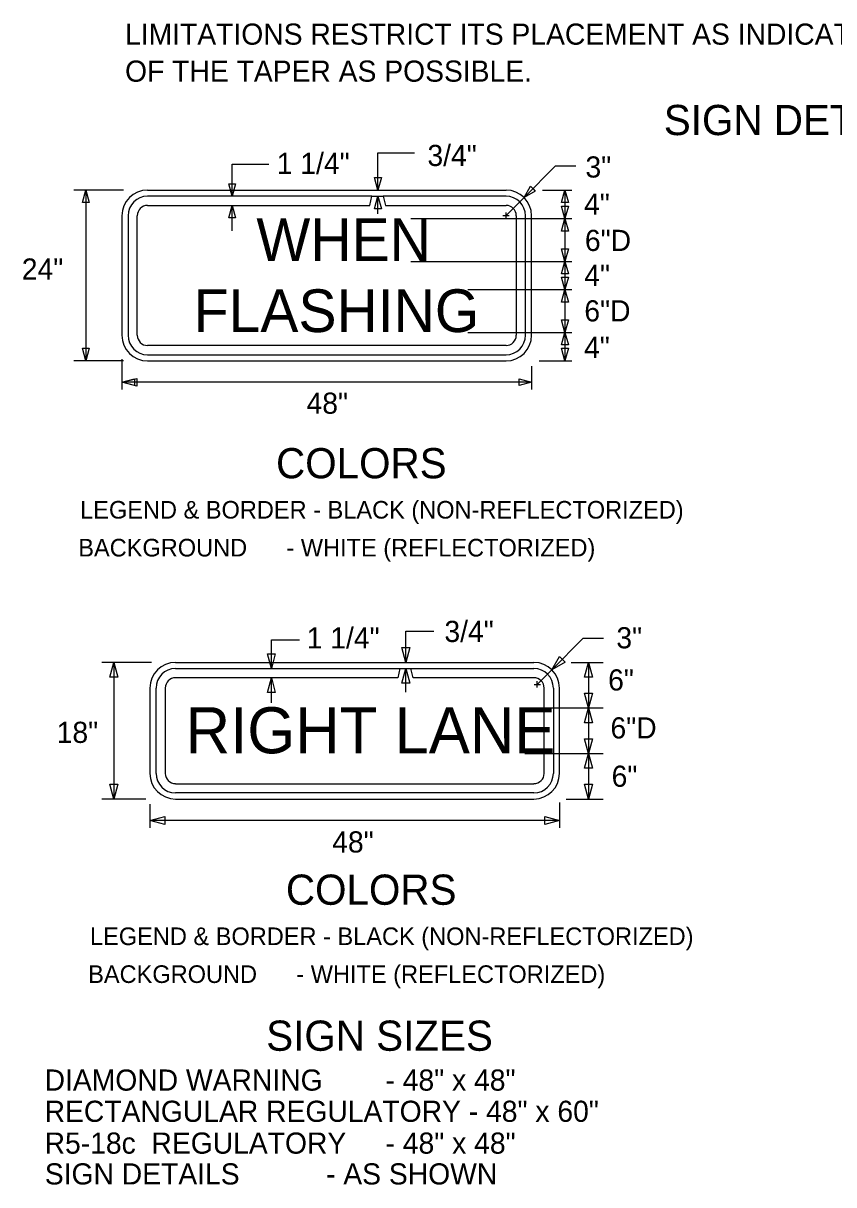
# Model space of a CAD drawing. Extents: x 15273 to 18137, y 1908 to 6555.
# Drawn here: x 17423.1 to 17745.2, y 2205.8 to 2667.1 of the extents above; entities that cross this region are included whole.
import ezdxf

# ---------------------------------------------------------------- set-up
doc = ezdxf.new("R2010")
doc.units = 0
for name, color, linetype in [('MT_SCRATCH_LEVEL_A', 7, 'Continuous'), ('TYPICAL_EX', 7, 'Continuous'), ('TYPICAL_TEXT_DIMEN_EX', 7, 'Continuous'), ('TYPICAL_TEXT_DIMEN_PR', 7, 'Continuous')]:
    doc.layers.add(name, color=color, linetype=linetype)

msp = doc.modelspace()

# ---------------------------------------------------------------- linework, layer by layer
at = {"layer": 'MT_SCRATCH_LEVEL_A'}
for p, q in [((17564.09, 2615.63), (17578.64, 2615.63)), ((17506.14, 2611.09), (17520.69, 2611.09)), ((17622.1, 2597.88), (17634.45, 2610.29)), ((17642.65, 2610.29), (17634.45, 2610.29)), ((17614.95, 2590.7), (17622.1, 2597.88)), ((17613.7, 2590.7), (17616.2, 2590.7)), ((17614.95, 2589.48), (17614.95, 2591.98)), ((17462.36, 2533.67), (17462.36, 2521.59)), ((17625.12, 2530.95), (17625.12, 2521.59)), ((17625.12, 2524.5), (17462.36, 2524.5)), ((17521.73, 2422.2), (17532.87, 2422.2)), ((17575.18, 2425.68), (17586.32, 2425.68)), ((17633.19, 2410.29), (17645.53, 2422.68)), ((17653.7, 2422.68), (17645.53, 2422.68)), ((17627.39, 2404.47), (17633.19, 2410.29)), ((17626.1, 2404.47), (17628.64, 2404.47)), ((17627.39, 2403.25), (17627.39, 2405.73)), ((17636.2, 2357.54), (17636.2, 2347.55)), ((17473.48, 2356.96), (17473.48, 2347.55)), ((17636.2, 2350.47), (17473.48, 2350.47))]:
    msp.add_line(p, q, dxfattribs=at)
at = {"layer": 'TYPICAL_EX'}
for p, q in [((17472.54, 2600.84), (17614.95, 2600.84)), ((17561.68, 2598.4), (17472.54, 2598.4)), ((17560.86, 2594.74), (17561.68, 2598.4)), ((17561.68, 2598.4), (17566.09, 2598.4)), ((17614.95, 2598.4), (17566.09, 2598.4)), ((17566.09, 2598.4), (17567.03, 2594.74)), ((17472.54, 2594.74), (17560.86, 2594.74)), ((17567.03, 2594.74), (17614.95, 2594.74)), ((17462.36, 2590.67), (17462.36, 2543.19)), ((17464.81, 2590.67), (17464.81, 2543.19)), ((17468.47, 2543.19), (17468.47, 2590.67)), ((17619.02, 2590.67), (17619.02, 2543.19)), ((17622.68, 2543.19), (17622.68, 2590.67)), ((17625.12, 2543.19), (17625.12, 2590.67)), ((17614.95, 2539.12), (17472.54, 2539.12)), ((17472.54, 2535.46), (17614.95, 2535.46)), ((17472.54, 2533.02), (17614.95, 2533.02)), ((17483.65, 2413.25), (17626.03, 2413.25)), ((17483.65, 2410.81), (17572.78, 2410.81)), ((17572.78, 2410.81), (17571.96, 2407.15)), ((17572.78, 2410.81), (17577.18, 2410.81)), ((17571.96, 2407.15), (17483.65, 2407.15)), ((17473.48, 2403.08), (17473.48, 2369.15)), ((17475.92, 2369.15), (17475.92, 2403.08)), ((17479.58, 2403.08), (17479.58, 2369.15)), ((17636.2, 2369.15), (17636.2, 2403.08)), ((17483.65, 2365.08), (17626.03, 2365.08)), ((17626.03, 2361.42), (17483.65, 2361.42)), ((17483.65, 2358.98), (17626.03, 2358.98))]:
    msp.add_line(p, q, dxfattribs=at)
for centre, radius, start, end in [((17472.54, 2590.67), 10.17, 90, 180), ((17472.54, 2590.67), 7.73, 90, 180), ((17614.95, 2590.67), 10.17, 0, 90), ((17614.95, 2590.67), 7.73, 0, 90), ((17472.54, 2590.67), 4.07, 90, 180), ((17614.95, 2590.67), 4.07, 0, 90), ((17472.54, 2543.18), 10.17, 180, 270), ((17472.54, 2543.18), 7.73, 180, 270), ((17472.54, 2543.18), 4.07, 180, 270), ((17614.95, 2543.18), 10.17, 270, 0), ((17614.95, 2543.18), 4.07, 270, 0), ((17614.95, 2543.18), 7.73, 270, 0), ((17483.65, 2403.08), 10.17, 90, 180), ((17626.03, 2403.08), 10.17, 0, 90), ((17483.65, 2403.08), 7.73, 90, 180), ((17483.65, 2403.08), 4.07, 90, 180), ((17483.65, 2369.16), 10.17, 180, 270), ((17483.65, 2369.16), 7.73, 180, 270), ((17483.65, 2369.16), 4.07, 180, 270), ((17626.03, 2369.16), 10.17, 270, 0), ((17626.03, 2369.16), 7.73, 270, 0), ((17626.03, 2369.16), 4.07, 270, 0)]:
    msp.add_arc(centre, radius, start, end, dxfattribs=at)
at = {"layer": 'TYPICAL_TEXT_DIMEN_PR'}
for p, q in [((17564.09, 2600.84), (17564.09, 2615.63)), ((17506.14, 2598.4), (17506.14, 2611.09)), ((17506.14, 2598.4), (17504.81, 2603.38)), ((17504.81, 2603.38), (17506.14, 2603.38)), ((17506.14, 2603.38), (17507.48, 2603.38)), ((17507.48, 2603.38), (17506.14, 2598.4)), ((17564.09, 2600.84), (17562.75, 2605.83)), ((17562.75, 2605.83), (17564.09, 2605.83)), ((17564.09, 2605.83), (17565.42, 2605.83)), ((17565.42, 2605.83), (17564.09, 2600.84)), ((17622.1, 2597.89), (17624.67, 2602.36)), ((17624.67, 2602.36), (17625.62, 2601.42)), ((17463.02, 2600.84), (17443.27, 2600.84)), ((17446.66, 2595.86), (17448, 2600.84)), ((17448, 2600.84), (17448, 2533.02)), ((17448, 2600.84), (17449.33, 2595.86)), ((17562.75, 2593.42), (17564.09, 2598.4)), ((17564.09, 2591.37), (17564.09, 2598.4)), ((17564.09, 2598.4), (17565.42, 2593.42)), ((17626.56, 2600.48), (17622.1, 2597.89)), ((17625.62, 2601.42), (17626.56, 2600.48)), ((17629.39, 2600.84), (17641.08, 2600.84)), ((17637.05, 2595.86), (17638.38, 2600.84)), ((17638.38, 2600.84), (17638.38, 2589.52)), ((17638.38, 2600.84), (17639.72, 2595.86)), ((17448, 2595.86), (17446.66, 2595.86)), ((17449.33, 2595.86), (17448, 2595.86)), ((17504.81, 2589.76), (17506.14, 2594.74)), ((17506.14, 2584.65), (17506.14, 2594.74)), ((17506.14, 2594.74), (17507.48, 2589.76)), ((17564.09, 2593.42), (17562.75, 2593.42)), ((17565.42, 2593.42), (17564.09, 2593.42)), ((17638.38, 2595.86), (17637.05, 2595.86)), ((17638.38, 2589.52), (17637.05, 2594.51)), ((17637.05, 2594.51), (17638.38, 2594.51)), ((17639.72, 2595.86), (17638.38, 2595.86)), ((17638.38, 2594.51), (17639.72, 2594.51)), ((17639.72, 2594.51), (17638.38, 2589.52)), ((17506.14, 2589.76), (17504.81, 2589.76)), ((17507.48, 2589.76), (17506.14, 2589.76)), ((17577.18, 2589.52), (17641.08, 2589.52)), ((17637.05, 2584.54), (17638.38, 2589.52)), ((17638.38, 2589.52), (17638.38, 2572.54)), ((17638.38, 2589.52), (17639.72, 2584.54)), ((17638.38, 2584.54), (17637.05, 2584.54)), ((17639.72, 2584.54), (17638.38, 2584.54)), ((17638.38, 2572.54), (17637.05, 2577.53)), ((17637.05, 2577.53), (17638.38, 2577.53)), ((17638.38, 2577.53), (17639.72, 2577.53)), ((17639.72, 2577.53), (17638.38, 2572.54)), ((17577.18, 2572.54), (17641.08, 2572.54)), ((17637.05, 2567.56), (17638.38, 2572.54)), ((17638.38, 2572.54), (17638.38, 2561.32)), ((17638.38, 2572.54), (17639.72, 2567.56)), ((17638.38, 2567.56), (17637.05, 2567.56)), ((17638.38, 2561.32), (17637.05, 2566.3)), ((17637.05, 2566.3), (17638.38, 2566.3)), ((17638.38, 2561.32), (17637.05, 2566.3)), ((17637.05, 2566.3), (17638.38, 2566.3)), ((17639.72, 2567.56), (17638.38, 2567.56)), ((17638.38, 2566.3), (17639.72, 2566.3)), ((17639.72, 2566.3), (17638.38, 2561.32)), ((17638.38, 2566.3), (17639.72, 2566.3)), ((17639.72, 2566.3), (17638.38, 2561.32)), ((17599.79, 2561.32), (17641.08, 2561.32)), ((17637.05, 2556.33), (17638.38, 2561.32)), ((17638.38, 2561.32), (17638.38, 2544.34)), ((17638.38, 2561.32), (17639.72, 2556.33)), ((17638.38, 2556.33), (17637.05, 2556.33)), ((17639.72, 2556.33), (17638.38, 2556.33)), ((17638.38, 2544.34), (17637.05, 2549.32)), ((17637.05, 2549.32), (17638.38, 2549.32)), ((17638.38, 2544.34), (17637.05, 2549.32)), ((17637.05, 2549.32), (17638.38, 2549.32)), ((17638.38, 2549.32), (17639.72, 2549.32)), ((17639.72, 2549.32), (17638.38, 2544.34)), ((17638.38, 2549.32), (17639.72, 2549.32)), ((17639.72, 2549.32), (17638.38, 2544.34)), ((17599.79, 2544.34), (17641.08, 2544.34)), ((17637.05, 2539.35), (17638.38, 2544.34)), ((17638.38, 2544.34), (17638.38, 2533.02)), ((17638.38, 2544.34), (17639.72, 2539.35)), ((17448, 2533.02), (17446.66, 2538)), ((17446.66, 2538), (17448, 2538)), ((17448, 2538), (17449.33, 2538)), ((17449.33, 2538), (17448, 2533.02)), ((17638.38, 2539.35), (17637.05, 2539.35)), ((17638.38, 2533.02), (17637.05, 2538)), ((17637.05, 2538), (17638.38, 2538)), ((17639.72, 2539.35), (17638.38, 2539.35)), ((17638.38, 2538), (17639.72, 2538)), ((17639.72, 2538), (17638.38, 2533.02)), ((17463.02, 2533.02), (17443.27, 2533.02)), ((17628.14, 2533.02), (17641.08, 2533.02)), ((17462.36, 2524.5), (17468.22, 2526.07)), ((17462.36, 2524.5), (17467.35, 2525.84)), ((17468.22, 2522.93), (17462.36, 2524.5)), ((17467.35, 2523.17), (17462.36, 2524.5)), ((17467.35, 2525.84), (17467.35, 2524.5)), ((17467.35, 2524.5), (17467.35, 2523.17)), ((17468.22, 2526.07), (17468.22, 2524.5)), ((17468.22, 2524.5), (17468.22, 2522.93)), ((17620.14, 2524.5), (17620.14, 2525.84)), ((17620.14, 2525.84), (17625.12, 2524.5)), ((17625.12, 2524.5), (17620.14, 2523.17)), ((17620.14, 2523.17), (17620.14, 2524.5)), ((17521.73, 2410.81), (17521.73, 2422.2)), ((17575.18, 2413.25), (17575.18, 2425.68)), ((17575.18, 2413.25), (17573.61, 2419.11)), ((17573.61, 2419.11), (17575.18, 2419.11)), ((17575.18, 2419.11), (17576.75, 2419.11)), ((17576.75, 2419.11), (17575.18, 2413.25)), ((17474.13, 2413.25), (17454.4, 2413.25)), ((17457.54, 2407.39), (17459.11, 2413.25)), ((17459.11, 2413.25), (17459.11, 2358.98)), ((17459.11, 2413.25), (17460.68, 2407.39)), ((17521.73, 2410.81), (17520.16, 2416.67)), ((17520.16, 2416.67), (17521.73, 2416.67)), ((17521.73, 2416.67), (17523.3, 2416.67)), ((17523.3, 2416.67), (17521.73, 2410.81)), ((17633.19, 2410.29), (17636.22, 2415.56)), ((17638.44, 2413.34), (17633.19, 2410.29)), ((17636.22, 2415.56), (17637.33, 2414.45)), ((17637.33, 2414.45), (17638.44, 2413.34)), ((17640.83, 2413.25), (17653.53, 2413.25)), ((17646.16, 2407.39), (17647.73, 2413.25)), ((17647.73, 2413.25), (17647.73, 2395.16)), ((17647.73, 2413.25), (17649.3, 2407.39)), ((17483.65, 2410.81), (17572.78, 2410.81)), ((17572.78, 2410.81), (17571.96, 2407.15)), ((17573.61, 2404.95), (17575.18, 2410.81)), ((17575.18, 2401.45), (17575.18, 2410.81)), ((17575.18, 2410.81), (17576.75, 2404.95)), ((17578.1, 2407.15), (17577.18, 2410.81)), ((17577.18, 2410.81), (17626.03, 2410.81)), ((17459.11, 2407.39), (17457.54, 2407.39)), ((17460.68, 2407.39), (17459.11, 2407.39)), ((17571.96, 2407.15), (17483.65, 2407.15)), ((17520.16, 2401.29), (17521.73, 2407.15)), ((17521.73, 2397.16), (17521.73, 2407.15)), ((17521.73, 2407.15), (17523.3, 2401.29)), ((17575.18, 2404.95), (17573.61, 2404.95)), ((17576.75, 2404.95), (17575.18, 2404.95)), ((17626.03, 2407.15), (17578.1, 2407.15)), ((17647.73, 2407.39), (17646.16, 2407.39)), ((17649.3, 2407.39), (17647.73, 2407.39)), ((17475.92, 2369.15), (17475.92, 2403.08)), ((17479.58, 2403.08), (17479.58, 2369.15)), ((17521.73, 2401.29), (17520.16, 2401.29)), ((17523.3, 2401.29), (17521.73, 2401.29)), ((17630.1, 2369.15), (17630.1, 2403.08)), ((17633.76, 2403.08), (17633.76, 2369.15)), ((17647.73, 2395.16), (17646.16, 2401.02)), ((17646.16, 2401.02), (17647.73, 2401.02)), ((17647.73, 2401.02), (17649.3, 2401.02)), ((17649.3, 2401.02), (17647.73, 2395.16)), ((17622.4, 2395.16), (17653.53, 2395.16)), ((17646.16, 2389.3), (17647.73, 2395.16)), ((17647.73, 2395.16), (17647.73, 2377.07)), ((17647.73, 2395.16), (17649.3, 2389.3)), ((17647.73, 2389.3), (17646.16, 2389.3)), ((17649.3, 2389.3), (17647.73, 2389.3)), ((17647.73, 2377.07), (17646.16, 2382.93)), ((17646.16, 2382.93), (17647.73, 2382.93)), ((17647.73, 2382.93), (17649.3, 2382.93)), ((17649.3, 2382.93), (17647.73, 2377.07)), ((17622.4, 2377.07), (17653.53, 2377.07)), ((17646.16, 2371.21), (17647.73, 2377.07)), ((17647.73, 2377.07), (17647.73, 2358.98)), ((17647.73, 2377.07), (17649.3, 2371.21)), ((17647.73, 2371.21), (17646.16, 2371.21)), ((17649.3, 2371.21), (17647.73, 2371.21)), ((17459.11, 2358.98), (17457.54, 2364.84)), ((17457.54, 2364.84), (17459.11, 2364.84)), ((17459.11, 2364.84), (17460.68, 2364.84)), ((17460.68, 2364.84), (17459.11, 2358.98)), ((17483.65, 2365.08), (17626.03, 2365.08)), ((17647.73, 2358.98), (17646.16, 2364.84)), ((17646.16, 2364.84), (17647.73, 2364.84)), ((17647.73, 2364.84), (17649.3, 2364.84)), ((17649.3, 2364.84), (17647.73, 2358.98)), ((17471.86, 2358.98), (17454.4, 2358.98)), ((17626.03, 2361.42), (17483.65, 2361.42)), ((17638.82, 2358.98), (17653.53, 2358.98)), ((17473.48, 2350.47), (17479.35, 2352.04)), ((17479.35, 2348.9), (17473.48, 2350.47)), ((17479.35, 2352.04), (17479.35, 2350.47)), ((17479.35, 2350.47), (17479.35, 2348.9)), ((17630.34, 2350.47), (17630.34, 2352.04)), ((17630.34, 2352.04), (17636.2, 2350.47)), ((17636.2, 2350.47), (17630.34, 2348.9)), ((17630.34, 2348.9), (17630.34, 2350.47))]:
    msp.add_line(p, q, dxfattribs=at)
for centre, radius, start, end in [((17483.65, 2403.08), 7.73, 90, 180), ((17626.03, 2403.08), 7.73, 0, 90), ((17483.65, 2403.08), 4.07, 90, 180), ((17626.03, 2403.08), 4.07, 0, 90), ((17483.65, 2369.16), 7.73, 180, 270), ((17483.65, 2369.16), 4.07, 180, 270), ((17626.03, 2369.16), 4.07, 270, 0), ((17626.03, 2369.16), 7.73, 270, 0)]:
    msp.add_arc(centre, radius, start, end, dxfattribs=at)

# ---------------------------------------------------------------- texts
at = {"layer": 'TYPICAL_TEXT_DIMEN_EX'}
for s, height, p in [('WHEN   ', 16.968, (17515.78, 2572.64)), ('FLASHING', 16.968, (17490.87, 2544.45)), ('RIGHT LANE', 18.308, (17487.68, 2377.13))]:
    msp.add_text(s, height=height, dxfattribs=at).set_placement(p)
at = {"layer": 'TYPICAL_TEXT_DIMEN_PR'}
for s, height, p in [('LIMITATIONS RESTRICT ITS PLACEMENT AS INDICATED, THEN IT SHALL BE PLACED AS CLOSE TO THE BEGINNING', 8.4, (17463.6, 2658.59)), ('OF THE TAPER AS POSSIBLE.', 8.4, (17463.6, 2643.89)), ('SIGN DETAILS', 12, (17677.65, 2622.68)), ('1 1/4"', 8.4, (17523.87, 2607.27)), ('3/4"', 8.4, (17583.73, 2610.41)), ('3"', 8.4, (17646.51, 2605.82)), ('4"', 8.4, (17645.96, 2591.05)), ('6"D', 8.4, (17646.3, 2576.66)), ('24"', 8.4, (17422.58, 2565.29)), ('4"', 8.4, (17646.04, 2562.79)), ('6"D', 8.4, (17646.07, 2548.69)), ('4"', 8.4, (17645.96, 2534.16)), ('48"', 8.4, (17535.71, 2512.01)), ('COLORS', 12, (17523.59, 2486.37)), ('LEGEND & BORDER - BLACK (NON-REFLECTORIZED)', 7, (17445.75, 2470.37)), ('BACKGROUND      - WHITE (REFLECTORIZED)', 7, (17445.02, 2455.32)), ('1 1/4"', 8.4, (17535.77, 2418.78)), ('3/4"', 8.4, (17590.48, 2421.36)), ('3"', 8.4, (17658.79, 2418.84)), ('6"', 8.4, (17655.52, 2402.09)), ('18"', 8.4, (17436.44, 2381.27)), ('6"D', 8.4, (17656.45, 2383.04)), ('6"', 8.4, (17656.91, 2363.85)), ('48"', 8.4, (17545.91, 2337.74)), ('COLORS', 12, (17527.51, 2316.98)), ('LEGEND & BORDER - BLACK (NON-REFLECTORIZED)', 7, (17449.68, 2300.97)), ('BACKGROUND      - WHITE (REFLECTORIZED)', 7, (17448.95, 2285.93)), ('SIGN SIZES', 12, (17519.68, 2258.99)), ('DIAMOND WARNING        - 48" x 48"', 8.4, (17431.64, 2243.16)), ('RECTANGULAR REGULATORY - 48" x 60"', 8.4, (17431.64, 2230.76)), ('R5-18c  REGULATORY     - 48" x 48"', 8.4, (17431.64, 2218.12)), ('SIGN DETAILS           - AS SHOWN', 8.4, (17431.72, 2205.89))]:
    msp.add_text(s, height=height, dxfattribs=at).set_placement(p)

doc.saveas('drawing.dxf')
